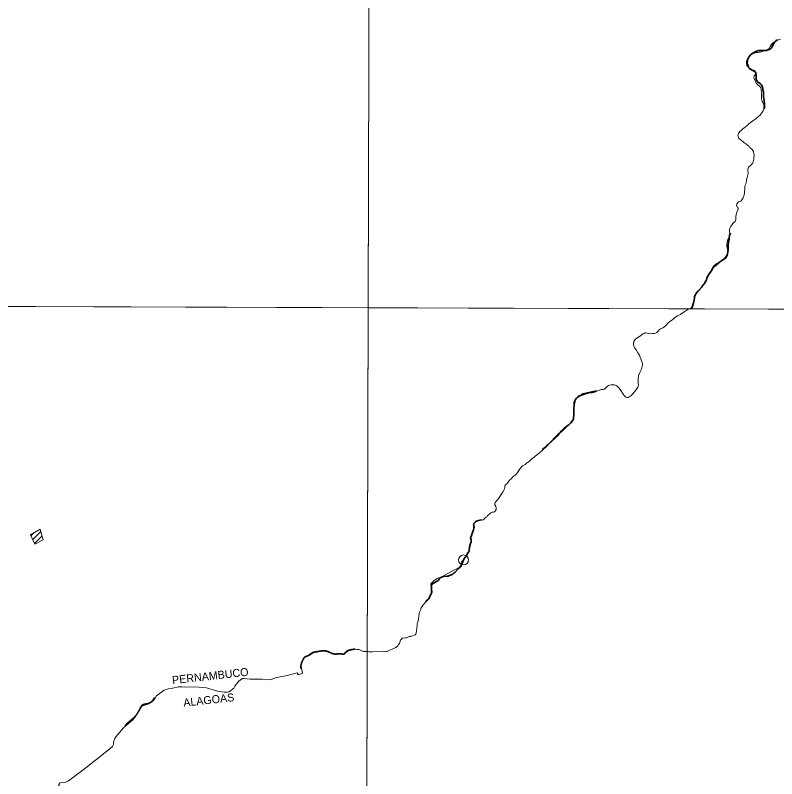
# Model space of a CAD drawing. Extents: x -1643653 to 4543381, y 1624270 to 13878484.
# Drawn here: x 582120 to 589726, y 8916321 to 8923949 of the extents above; entities that cross this region are included whole.
import ezdxf
from ezdxf.enums import TextEntityAlignment as Align

# ---------------------------------------------------------------- set-up
doc = ezdxf.new("R2010")
doc.units = 0
doc.header["$LTSCALE"] = 200
doc.header["$PDMODE"] = 32
doc.header["$PDSIZE"] = 100
doc.linetypes.add('LONG_DASH_SHORT_DASH', pattern=[9.9, 6, -1.2, 1.5, -1.2])
doc.layers.add('1', color=7, linetype='Continuous', lineweight=13)
doc.layers.add('6', color=7, linetype='Continuous', lineweight=13)

msp = doc.modelspace()

# ---------------------------------------------------------------- linework, layer by layer
at = {"layer": '1', "lineweight": 25}
msp.add_spline([(814781, 9009175.5), (814787.2, 9009173.4), (814796.9, 9009173.4), (814799.4, 9009172.4), (814805.1, 9009174.5), (814805.6, 9009176.5), (814811.7, 9009179.5), (814811.7, 9009179.5), (814801.5, 9009181), (814790.7, 9009181.5), (814784.1, 9009183.1), (814777.4, 9009185.1), (814778.4, 9009175.5)], degree=3, dxfattribs=at)
at = {"layer": '6'}
for p, q in [((582276.5, 8918748), (582308.9, 8918780.4)), ((582294.7, 8918709.6), (582376.4, 8918791.3)), ((582312.9, 8918671.2), (582388.6, 8918746.9))]:
    msp.add_line(p, q, dxfattribs=at)
at = {"layer": '6', "linetype": 'LONG_DASH_SHORT_DASH', "lineweight": 35}
msp.add_line((585799, 8917597.9), (585799.3, 8917597.8), dxfattribs=at)
at = {"layer": '6'}
for points in [[(585656.3, 8924738.8), (585614.8, 8909969.8), (585573.6, 8896026.7)], [(589516.7, 8923577.1), (589538.1, 8923578.1), (589548.8, 8923580.6), (589560.2, 8923581.6), (589569.4, 8923583.3), (589579.4, 8923585.8), (589590.3, 8923590.3), (589607, 8923592.8), (589610.7, 8923593), (589621.2, 8923596.4), (589631.2, 8923602.7), (589640.6, 8923608.9), (589649, 8923617.2), (589661.2, 8923635.9), (589671.7, 8923653.4), (589678, 8923660.6), (589684.5, 8923668.9), (589692.2, 8923676.6), (589712.7, 8923690.4), (589723, 8923695), (589763.3, 8923710.2)], [(589500.8, 8923316.4), (589497.4, 8923327.4), (589499.4, 8923339.3), (589501, 8923341.2), (589502, 8923343.6), (589509.3, 8923353.2), (589510.9, 8923357.4), (589513.7, 8923360.2), (589514.2, 8923361.5), (589515.2, 8923369.6), (589514, 8923378.3), (589507.6, 8923392.2), (589502.1, 8923396.1), (589495.2, 8923398.9), (589475, 8923406.2), (589463.6, 8923412.9), (589453.8, 8923420.2), (589443.6, 8923429), (589435.7, 8923436.2), (589428.2, 8923446.1), (589425.5, 8923454), (589424.1, 8923463.2), (589422.2, 8923489.5), (589423.2, 8923490.8), (589430, 8923506.7), (589434.9, 8923512.9), (589439.6, 8923519.5), (589449.5, 8923531.9), (589454.7, 8923539.7), (589458.4, 8923543.1), (589459.4, 8923547.2), (589461.9, 8923548.3), (589474.8, 8923558.2), (589516.7, 8923577.1)], [(589512.2, 8923285.9), (589505.5, 8923301.3), (589500.8, 8923316.4)], [(589338.9, 8922741.2), (589338.8, 8922746.3), (589340.7, 8922759.1), (589343.2, 8922767.2), (589348.9, 8922777), (589356.6, 8922785.8), (589359.8, 8922791.1), (589362.2, 8922793.4), (589369.6, 8922799), (589373.1, 8922802.4), (589379.9, 8922807.3), (589387.7, 8922815.1), (589392.1, 8922817.7), (589396.6, 8922820.9), (589400.9, 8922823.2), (589407.8, 8922827.8), (589410.8, 8922830), (589417.8, 8922837), (589427.9, 8922845.1), (589432.4, 8922849.7), (589443.9, 8922858.7), (589448.7, 8922863.3), (589478.5, 8922888.2), (589483.8, 8922891.4), (589496.7, 8922900.7), (589507.2, 8922907.3), (589516.2, 8922913.7), (589520.7, 8922917.5), (589525.2, 8922921.8), (589536.8, 8922931.1), (589539.5, 8922934.5), (589544.3, 8922939.2), (589547.5, 8922941.3), (589550.8, 8922944.3), (589556, 8922947.7), (589559.1, 8922950.1), (589567.9, 8922959.8), (589570.8, 8922963.9), (589573.4, 8922969), (589575.7, 8922972.4), (589584.2, 8922983.5), (589586.3, 8922987.3), (589589.4, 8922994.1), (589591.3, 8923001.8), (589593.9, 8923009.7), (589595.6, 8923016.5), (589598.2, 8923032.3), (589598.3, 8923038.9), (589598.8, 8923046), (589598.1, 8923052), (589594.3, 8923064.6), (589586.6, 8923077.4), (589581.5, 8923087.3), (589579.4, 8923090.2), (589576.8, 8923096.9), (589574.8, 8923115.9), (589574.7, 8923128.7), (589572.2, 8923141.7), (589572.1, 8923166.5), (589571.4, 8923174.8), (589572, 8923181.2), (589572, 8923187.4), (589570.7, 8923193.9), (589570.6, 8923200.3), (589569.4, 8923206.9), (589568.7, 8923215.2), (589566.8, 8923223.1), (589565.5, 8923223.8), (589565.2, 8923226.3), (589560, 8923234), (589552.3, 8923240.3), (589538.4, 8923254.4), (589519, 8923270.7), (589512.2, 8923285.9)], [(589460.2, 8922445.9), (589466.4, 8922450.1), (589476.2, 8922460.4), (589478.9, 8922461), (589479.3, 8922463.1), (589485.5, 8922471.9), (589489.5, 8922483.1), (589494.3, 8922502.3), (589496.3, 8922513.2), (589498.7, 8922533.1), (589498.8, 8922543.7), (589499.9, 8922553.6), (589498.6, 8922564.5), (589495.3, 8922585.8), (589493.7, 8922587.8), (589487.6, 8922597.4), (589480, 8922606.1), (589458, 8922627), (589457.7, 8922628.5), (589456.1, 8922628.9), (589455.7, 8922631.9), (589451.9, 8922634.7), (589447.8, 8922642.2), (589427.8, 8922657), (589418, 8922663.8), (589407.5, 8922670.3), (589398, 8922677.1), (589389.1, 8922685.1), (589376.8, 8922695.6), (589372.3, 8922698.8), (589371.6, 8922700.5), (589347.3, 8922716.4), (589346.4, 8922718.1), (589338.9, 8922741.2)], [(589006.9, 8921286.1), (589017.7, 8921298.2), (589025.9, 8921311.4), (589032.3, 8921323.1), (589038.7, 8921335.9), (589044.8, 8921346.8), (589061.1, 8921374.5), (589062.1, 8921375.7), (589065.5, 8921376.8), (589066.3, 8921377.4), (589067.9, 8921382.3), (589080.2, 8921406.4), (589088.1, 8921416.9), (589095.6, 8921428.2), (589103, 8921436.9), (589114.8, 8921446.2), (589127.9, 8921454.3), (589138.6, 8921462.4), (589156.6, 8921481.7), (589166.2, 8921490.8), (589178.1, 8921500.6), (589191.4, 8921510), (589200.1, 8921518.9), (589210.1, 8921529.4), (589229.5, 8921558.3), (589234.5, 8921575.8), (589235.7, 8921589), (589233, 8921614.5), (589230.5, 8921626.8), (589227.1, 8921641), (589225.9, 8921651.4), (589226.5, 8921662.7), (589229.7, 8921674.9), (589234.2, 8921697.9), (589238.6, 8921709.2), (589245.8, 8921721.4), (589253.2, 8921743.4), (589255.8, 8921757.4), (589255.8, 8921769.2), (589254.4, 8921783), (589254.5, 8921808.2), (589258.8, 8921821.3), (589264.6, 8921833.6), (589274, 8921849.4), (589285.7, 8921867.3), (589287, 8921868.7), (589298.2, 8921877), (589311.8, 8921888.1), (589315.3, 8921895.6), (589317.8, 8921908.2), (589317.8, 8921921), (589318.4, 8921933.5), (589321, 8921959.8), (589324.1, 8921972.4), (589328.4, 8921984.8), (589339.9, 8922008.6), (589340.7, 8922010.8), (589340.6, 8922020.6), (589340.4, 8922021.9), (589337.5, 8922025.1), (589335.1, 8922031.9), (589330.5, 8922037.5), (589325.3, 8922042.9), (589326.5, 8922064), (589345, 8922085.2), (589367.2, 8922093.1), (589369, 8922094.1), (589390.3, 8922123.7), (589395, 8922136.7), (589398.9, 8922149.8), (589403.8, 8922174.9), (589403.9, 8922188.4), (589406.4, 8922213.6), (589406.4, 8922226.6), (589408.3, 8922239.4), (589411.4, 8922251.8), (589416.5, 8922265), (589419.7, 8922277.8), (589423.4, 8922290.4), (589424.8, 8922303.8), (589429.7, 8922328.4), (589434.3, 8922342), (589437.6, 8922355.6), (589439.4, 8922368.3), (589439.3, 8922380.6), (589438, 8922393.7), (589438.1, 8922406.5), (589445.3, 8922432.1), (589460.2, 8922445.9)], [(588894.1, 8921078.3), (588899.6, 8921098.8), (588904.2, 8921126.1), (588914.3, 8921152.8), (588920.1, 8921165.7), (588925.5, 8921176.6), (588933.3, 8921185.3), (588950, 8921200.7), (588958.1, 8921209.6), (588965.2, 8921218.7), (588971.4, 8921228.1), (588977.2, 8921237.7), (588983.2, 8921246), (588992.1, 8921255.2), (589001.3, 8921265.6), (589006.1, 8921273.9), (589006.9, 8921286.1)], [(574684.9, 8921064.7), (596639.8, 8920989.8), (607636.3, 8920937.2), (626625.7, 8920820.5)], [(588866, 8921014.8), (588889.6, 8921061.5), (588894.1, 8921078.3)], [(588655.6, 8920885.9), (588677.4, 8920901.9), (588686.9, 8920909.9), (588701.1, 8920923.5), (588708.3, 8920929.1), (588735.8, 8920945.1), (588763.3, 8920958.1), (588772.3, 8920964.5), (588787.3, 8920977.1), (588811.4, 8920991.1), (588822.9, 8921000.3), (588834.6, 8921008.1), (588849.2, 8921013.6), (588866, 8921014.8)], [(588133.1, 8920242.8), (588149.7, 8920226.2), (588162.1, 8920210.6), (588192.2, 8920163.2), (588200.8, 8920151.2), (588210.3, 8920141), (588218.2, 8920134.2), (588229.5, 8920131.2), (588239.4, 8920130.6), (588242.6, 8920131.2), (588252.2, 8920136.2), (588263.6, 8920144.6), (588274.1, 8920153.8), (588286.8, 8920167.4), (588317.7, 8920204.6), (588338.9, 8920234.8), (588341.5, 8920240.4), (588344.1, 8920258), (588343.1, 8920273.4), (588340.8, 8920288.6), (588341.3, 8920325.6), (588343.4, 8920340), (588346, 8920349.4), (588356.8, 8920379.2), (588371.2, 8920405), (588375.2, 8920414.2), (588383.2, 8920440), (588384.8, 8920451.4), (588384.9, 8920464.6), (588382.6, 8920479), (588371.7, 8920504.6), (588359.6, 8920544.4), (588355, 8920553.2), (588348.1, 8920563.6), (588339.4, 8920574.6), (588322.3, 8920605), (588308.9, 8920623.2), (588298.6, 8920647.4), (588295.4, 8920660.6), (588295.9, 8920674.4), (588299.2, 8920688.8), (588303.9, 8920701), (588310.3, 8920711), (588316.9, 8920717), (588354.3, 8920738), (588383.7, 8920762), (588395.1, 8920768.6), (588407.3, 8920773.8), (588413, 8920775.2), (588418.4, 8920774.8), (588460.6, 8920766.8), (588487.3, 8920768.8), (588503.7, 8920768.2), (588522.2, 8920775.8), (588526.8, 8920778.8), (588537.4, 8920788.2), (588548.5, 8920803.2), (588555.8, 8920810.9), (588564.9, 8920816.8), (588587.7, 8920826.9), (588603.8, 8920836.1), (588610.7, 8920843.9), (588624, 8920855.9), (588641.9, 8920874.5), (588655.5, 8920886.1)], [(587691.5, 8919899.2), (587695.6, 8919912), (587699.2, 8919964.2), (587697.5, 8919992.4), (587697.6, 8920004.6), (587700.8, 8920020), (587703.5, 8920044.2), (587710.4, 8920069), (587712.5, 8920094.4), (587714.5, 8920104.2), (587717.9, 8920111), (587723, 8920118), (587730.8, 8920125.6), (587748.4, 8920136.4), (587759.7, 8920142.4), (587778.2, 8920150.6), (587804, 8920160), (587849.8, 8920172.2), (587870.3, 8920176.6), (587885.6, 8920178.2), (587910.3, 8920183.8), (587917, 8920186.6), (587930.3, 8920193.8), (587965.5, 8920207.4), (587974.1, 8920208.8), (587989.3, 8920209.2), (587999.8, 8920211.8), (588005.2, 8920214.8), (588016.8, 8920224), (588035.3, 8920241.8), (588046.8, 8920250.6), (588055.4, 8920254.4), (588071.6, 8920256.6), (588094, 8920257.2), (588104.9, 8920255.8), (588121.9, 8920249.6), (588133.1, 8920242.8)], [(586916.9, 8918999.4), (586921.8, 8919011.7), (586923.2, 8919017.8), (586923.8, 8919027.8), (586919.9, 8919040.7), (586909.9, 8919057.1), (586909, 8919064.2), (586909.4, 8919069.7), (586914.4, 8919080.4), (586932.4, 8919104.2), (586949.8, 8919125.1), (586961.5, 8919140.2), (586992.8, 8919190.2), (587002.7, 8919209.4), (587006.2, 8919218.4), (587008.9, 8919230.4), (587010.4, 8919247.4), (587012.9, 8919254.6), (587016, 8919258.6), (587035, 8919274.8), (587055.6, 8919302.4), (587072, 8919316.4), (587094, 8919340.4), (587112.3, 8919355.2), (587126.1, 8919368.8), (587137.1, 8919382), (587155.1, 8919411), (587172.6, 8919433.8), (587187.4, 8919446.2), (587211.4, 8919462), (587226.2, 8919474.8), (587234.8, 8919481.4), (587256, 8919495), (587279.1, 8919516.8), (587302.2, 8919534.6), (587313.3, 8919545), (587338.1, 8919562.4), (587360.9, 8919581.2), (587383.5, 8919602), (587399.3, 8919618), (587418.7, 8919633.8), (587431.5, 8919646.8), (587438.1, 8919658.2), (587442.8, 8919664), (587447.3, 8919667.4), (587454, 8919670.8), (587465.3, 8919679.2), (587481.8, 8919698.6), (587488.5, 8919705), (587509.1, 8919720), (587523.9, 8919732.2), (587542.4, 8919750.6), (587556.5, 8919769.4), (587562.2, 8919775.8), (587583.5, 8919793.8), (587602, 8919814.2), (587611.3, 8919821.8), (587622.8, 8919832.8), (587643.4, 8919849.8), (587655.9, 8919864), (587663.9, 8919871.6), (587678.6, 8919882), (587683.7, 8919887), (587691.5, 8919899.2), (587691.5, 8919899.2)], [(586679.6, 8918760.5), (586680.3, 8918772.5), (586692.5, 8918786.5), (586696.8, 8918798.9), (586696.9, 8918809.3), (586697.7, 8918812.7), (586699.3, 8918815.3), (586704.2, 8918820.1), (586707.7, 8918826.9), (586707.4, 8918834.5), (586702.6, 8918847.7), (586701.8, 8918857.5), (586703.1, 8918864.1), (586709.7, 8918881.3), (586721, 8918893.5), (586725.9, 8918895.7), (586766.1, 8918904.9), (586782.2, 8918905.1), (586794.3, 8918909.1), (586801.8, 8918914.7), (586808.8, 8918923.3), (586813, 8918927.3), (586824.3, 8918933.9), (586830.1, 8918938.5), (586834.8, 8918944.1), (586841.9, 8918955.9), (586845.8, 8918960.3), (586848.8, 8918962.4), (586859.7, 8918966.8), (586863.7, 8918970.4), (586869.3, 8918977.4), (586877.2, 8918981.7), (586883.6, 8918984.1), (586895.7, 8918985.2), (586905.7, 8918987.4), (586911.9, 8918992.7), (586916.9, 8918999.4)], [(586136.8, 8917879.9), (586143.9, 8917898.3), (586146.5, 8917907.1), (586150.7, 8917947.5), (586156.3, 8917986.5), (586166.2, 8918006.3), (586175.4, 8918028.7), (586186.6, 8918050.1), (586197.8, 8918063.5), (586206.1, 8918071.9), (586225, 8918098.7), (586234.8, 8918109.9), (586249.5, 8918120.5), (586256.8, 8918127.7), (586261.3, 8918135.7), (586262.8, 8918149.5), (586276.3, 8918165.5), (586281.8, 8918176.7), (586282.8, 8918182.3), (586282.8, 8918191.1), (586279.2, 8918209.5), (586279.1, 8918219.3), (586275.1, 8918241.3), (586270.8, 8918255.1), (586270.6, 8918261.3), (586271.5, 8918267.7), (586278.2, 8918274.1), (586295.8, 8918294.9), (586307.4, 8918303.7), (586335.1, 8918320.1), (586377.8, 8918336.7), (586395.1, 8918344.9), (586480.1, 8918393.5), (586505.7, 8918406.7), (586524.1, 8918414.9), (586554, 8918433.1), (586568.4, 8918447.3), (586570.6, 8918451.1), (586575.7, 8918463.9), (586578.3, 8918475.3), (586579.7, 8918491.9), (586595.5, 8918507.3), (586602.8, 8918522.3), (586607.5, 8918529.5), (586619.7, 8918540.1), (586627.3, 8918548.9), (586630.1, 8918555.5), (586632.3, 8918569.5), (586634.1, 8918575.1), (586636.7, 8918579.5), (586645.9, 8918589.1), (586648.8, 8918594.9), (586650.6, 8918604.3), (586653.5, 8918631.7), (586658.1, 8918644.7), (586665.3, 8918659.3), (586672.6, 8918692.7), (586672.6, 8918710.3), (586671.1, 8918715.7), (586665.9, 8918726.3), (586666, 8918731.5), (586668, 8918736.7), (586678.5, 8918755.1), (586678.5, 8918755.1), (586679.6, 8918760.5)], [(585824.4, 8917592.5), (585835.6, 8917593.5), (585848.5, 8917598.3), (585866.6, 8917609.5), (585883, 8917614.7), (585896.8, 8917622.9), (585921, 8917633.3), (585928.7, 8917638.5), (585940.3, 8917649.7), (585947.5, 8917662.7), (585957.1, 8917673.5), (585961.2, 8917682.5), (585965.9, 8917699.7), (585968.9, 8917706.9), (585976, 8917717.1), (585984.1, 8917723.9), (585988.6, 8917725.7), (585994.5, 8917727.1), (586017.6, 8917728.5), (586028.1, 8917729.9), (586035.3, 8917731.9), (586054, 8917741.3), (586060.6, 8917742.5), (586070, 8917742.7), (586088.9, 8917750.3), (586104.1, 8917754.3), (586112.5, 8917757.7), (586118, 8917762.1), (586120.7, 8917766.5), (586122.9, 8917773.1), (586126.9, 8917800.7), (586130.7, 8917821.1), (586131.4, 8917832.3), (586133.7, 8917846.3), (586134.3, 8917870.5), (586136.8, 8917879.9)], [(584946, 8917362.1), (584956.7, 8917362.1), (584984.5, 8917371.3), (584987.1, 8917382.3), (584980.7, 8917404.5), (584974.8, 8917448.6), (584983.7, 8917481.7), (584998.1, 8917514.8), (585010.1, 8917531), (585049.8, 8917550.4), (585085.7, 8917573.9), (585106.9, 8917582), (585162.1, 8917591.8), (585206.3, 8917594.7), (585224.1, 8917592.2)], [(585406.5, 8917564.6), (585417.5, 8917578), (585441.3, 8917595.2), (585463.8, 8917604.5), (585514.8, 8917615.6), (585533.1, 8917613.4)], [(585533.1, 8917613.4), (585551.5, 8917611.2), (585597.6, 8917591.8)], [(585224.1, 8917592.2), (585233.4, 8917590.9), (585273.5, 8917573.1), (585302.3, 8917565), (585331.2, 8917562.9), (585406.5, 8917564.6)], [(585597.6, 8917591.8), (585645.8, 8917591.3), (585655.1, 8917588.7), (585668.4, 8917587.5), (585687.5, 8917587.3), (585824.4, 8917592.5)], [(584562.5, 8917316.2), (584584.8, 8917316), (584661, 8917309.7), (584679.6, 8917312.2), (584715.2, 8917328.8), (584836.7, 8917352.1), (584920.8, 8917375.9), (584935.7, 8917377.6), (584946, 8917362.1)], [(584289.7, 8917215.3), (584302.2, 8917227.5), (584311.2, 8917245.5), (584349.8, 8917291.8), (584386.3, 8917322.1), (584405.1, 8917324.1), (584466.3, 8917316.9), (584511.8, 8917316.6), (584562.5, 8917316.2)], [(583605.6, 8917205.9), (583606.2, 8917206.4), (583647.1, 8917217.9), (583691.7, 8917225.1), (583694.7, 8917225.9)], [(583694.7, 8917225.9), (583751.3, 8917239.9), (583784.8, 8917238.2)], [(583784.8, 8917238.2), (583823, 8917236.2), (583913.9, 8917240), (584030.3, 8917229.4), (584139.1, 8917197.5), (584207.1, 8917184.8), (584241.1, 8917186), (584254.7, 8917190.7), (584281.9, 8917207.8), (584289.7, 8917215.3)], [(583497.2, 8917101.5), (583513.7, 8917119.7), (583530.7, 8917150.3), (583605.6, 8917205.9)], [(583374.4, 8917029.3), (583384.1, 8917046.7), (583454.1, 8917069.1), (583484.8, 8917087.9), (583497.2, 8917101.5)], [(583110.2, 8916714.5), (583112.9, 8916723.3), (583122.7, 8916738.7), (583200.6, 8916830.8), (583293.7, 8916911.2), (583311.9, 8916931.1), (583355.3, 8916994.9), (583374.4, 8917029.3)], [(583090.8, 8916642.8), (583100.4, 8916661.6), (583101.2, 8916686.4), (583110.2, 8916714.5)], [(582550.9, 8916251), (582561.6, 8916267.1), (582557.7, 8916274.2), (582569.7, 8916279), (582618.1, 8916284.9), (582650.7, 8916300), (582838.2, 8916439.2), (582906.1, 8916497.3), (582963.8, 8916539.2), (583090.8, 8916642.8)]]:
    msp.add_lwpolyline(points, dxfattribs=at)
for points in [[(585656.3, 8924738.8), (596655.5, 8924715.8), (596639.8, 8920989.8), (585645.8, 8921027.3)], [(585645.8, 8921027.3), (574684.9, 8921064.7), (574653.9, 8910009.3), (585614.8, 8909969.8)], [(582271.3, 8918759), (582316.7, 8918663.1), (582399.6, 8918706.8), (582369.9, 8918815)]]:
    msp.add_lwpolyline(points, close=True, dxfattribs=at)
at = {"layer": '6', "linetype": 'LONG_DASH_SHORT_DASH', "lineweight": 35}
for points in [[(589732.9, 8923704.4), (589720.4, 8923696.8), (589711.9, 8923686.3), (589703.9, 8923675.2), (589686.9, 8923648.5), (589679.9, 8923633.9), (589669.4, 8923618.8), (589654.3, 8923608.2), (589639.8, 8923602.6), (589624.2, 8923598), (589606.1, 8923597.4), (589577.5, 8923597.3), (589547.8, 8923595.2), (589516.7, 8923586.5), (589487.6, 8923569.3), (589474.1, 8923560.2), (589463, 8923552.1), (589450, 8923535.5), (589443, 8923523.4), (589434.5, 8923504.3), (589433.6, 8923489.7), (589432.1, 8923474.7), (589432.2, 8923458.6), (589438.8, 8923442), (589443.9, 8923427), (589454, 8923417.5), (589481.2, 8923399), (589495.2, 8923394.6), (589508.3, 8923387.6), (589517.5, 8923372.6), (589521, 8923358.5), (589521.1, 8923325.4), (589521.7, 8923309.8), (589526.8, 8923294.8), (589535.4, 8923281.8), (589550, 8923273.8)], [(589550, 8923273.8), (589562.6, 8923262.8), (589572.7, 8923252.8), (589580.3, 8923236.7), (589585.3, 8923220.2), (589588.4, 8923200.6), (589592.5, 8923183.1), (589592.6, 8923164), (589594.7, 8923132.3), (589596.3, 8923117.3), (589599.3, 8923103.2), (589600.9, 8923089.7), (589603.5, 8923071.6), (589604, 8923056.6), (589604.1, 8923041.5), (589603.6, 8923025.4), (589601.5, 8923015.4)], [(589262.4, 8921776.3), (589254.8, 8921747.1), (589251.8, 8921726), (589251.4, 8921710.4), (589247.4, 8921693.8), (589239.5, 8921655.1), (589239.6, 8921610.4), (589237.7, 8921580.3), (589235.3, 8921563.7), (589231.3, 8921549.6), (589215.3, 8921521.4), (589132.6, 8921468.3), (589120.5, 8921461.2), (589098, 8921441), (589090.5, 8921429.4), (589084, 8921417.3), (589078.5, 8921402.8), (589050.5, 8921365.4), (589040.5, 8921350.3), (589033.5, 8921337.8), (589029, 8921322.2), (589025.5, 8921307.1), (589017.5, 8921291.5), (589010.5, 8921279.4), (589002, 8921266.3), (588982.5, 8921240.6), (588974, 8921227.5), (588964.5, 8921217.4), (588950.5, 8921205.3), (588938.9, 8921193.2), (588929.9, 8921182.6), (588918.9, 8921166.4), (588912.4, 8921152.3), (588906, 8921134.7), (588905.5, 8921121.2), (588902, 8921105.6), (588899.1, 8921090), (588894.1, 8921076.4), (588881.2, 8921032.6), (588876.7, 8921019.1), (588873.6, 8921014.8)], [(587701.6, 8920064.6), (587703.2, 8920080.8), (587707.8, 8920095.9), (587711, 8920103.7), (587715.3, 8920111.1), (587726.9, 8920123.9), (587733.5, 8920129.9), (587738.1, 8920135.1), (587744.4, 8920140.8), (587750.3, 8920144.2), (587771.1, 8920154.8), (587778.3, 8920159.7), (587792.9, 8920165.5), (587808.5, 8920171.2), (587837.1, 8920177.3), (587851.6, 8920180.9), (587880.5, 8920185.8), (587895.1, 8920188.6), (587902.5, 8920190.3), (587916.5, 8920192.8), (587924.1, 8920195.4), (587926.9, 8920195.9)], [(587384.3, 8919609.4), (587392.8, 8919616.3), (587405.5, 8919627.7), (587412.1, 8919632.4), (587417.9, 8919638.4), (587424.8, 8919644.2), (587430.4, 8919650.8), (587441.5, 8919662), (587541.8, 8919762.6), (587551.1, 8919770.1), (587557.9, 8919776), (587563.2, 8919781.1), (587576.3, 8919795.3), (587583.5, 8919804.2), (587591.3, 8919812.9), (587606.1, 8919826.6), (587612.5, 8919831.4), (587618.5, 8919836.6), (587624.4, 8919840.8), (587631.5, 8919846.6), (587642.7, 8919854.2), (587649.1, 8919858.2), (587655, 8919862.8), (587659.9, 8919868.4), (587664.8, 8919874.6), (587695.6, 8919913.3), (587697.2, 8919915.7), (587699.1, 8919965.1), (587698.6, 8919973.8), (587699.4, 8919981), (587699.3, 8919988.3), (587699.9, 8919996), (587699.5, 8920003.7), (587699.7, 8920011.4), (587699.3, 8920019.1), (587700.3, 8920027), (587701.3, 8920041), (587701.6, 8920049.7), (587701.4, 8920057.6), (587701.6, 8920064.6)], [(586698.2, 8918860.5), (586699.5, 8918868.4), (586701.6, 8918872.3), (586709.1, 8918881.7), (586716.2, 8918889), (586725.8, 8918894.1), (586735.2, 8918897.5), (586743.7, 8918899.7), (586775.5, 8918907)], [(586597.6, 8918506.7), (586605.9, 8918523.4), (586611.9, 8918529.9), (586617.3, 8918534), (586622.3, 8918538.9), (586623.4, 8918540.9), (586626.4, 8918548.8), (586631.3, 8918557.1), (586634.3, 8918565.1), (586637.8, 8918573), (586643.9, 8918581.7), (586648.8, 8918589.4), (586652.3, 8918595.6), (586654.7, 8918605.5), (586654.8, 8918613.8), (586656.7, 8918622.1), (586657.8, 8918638.2), (586659.7, 8918646.3), (586661, 8918654.2), (586663.5, 8918662.4), (586666.6, 8918670.9), (586668.9, 8918678.8), (586672.1, 8918687.1), (586672.3, 8918702.8), (586672, 8918712), (586671, 8918719.4), (586667.1, 8918727.6), (586666.9, 8918728.6), (586672.8, 8918742), (586679.1, 8918756), (586680.9, 8918764.7), (586683.4, 8918772.6), (586688.5, 8918781.8), (586690.3, 8918790.4), (586695.8, 8918807.9), (586701.3, 8918821.4), (586701.6, 8918825.4), (586701.4, 8918834.4), (586699.1, 8918851.1), (586698.2, 8918860.5)], [(586513.5, 8918384.7), (586547.2, 8918421.3), (586562.5, 8918435.2), (586568.8, 8918442), (586573.9, 8918450.3), (586577.2, 8918457.8), (586580, 8918465.9), (586583.2, 8918474), (586594.1, 8918498), (586597.6, 8918506.7)], [(586222.6, 8918087.9), (586223.9, 8918090.1), (586228.4, 8918096.1), (586236.5, 8918103.6), (586243.8, 8918110.9), (586250.2, 8918118.5), (586254.6, 8918126.4), (586260.8, 8918142.7), (586268.8, 8918158.2), (586272.8, 8918166.7), (586277.2, 8918183.1), (586278.1, 8918191.2), (586277.5, 8918199.5), (586276, 8918207.8), (586276, 8918223.7), (586276.6, 8918240), (586275.8, 8918254), (586276.7, 8918256.6), (586280.2, 8918263.9), (586287.4, 8918268.9), (586293.9, 8918272.7), (586327.8, 8918291.2), (586334.7, 8918295.4), (586343.5, 8918302.7), (586357.8, 8918319.5), (586363.1, 8918326.4), (586369.2, 8918332), (586377.3, 8918336.3), (586385.6, 8918339.6), (586393.6, 8918341.5), (586401.5, 8918342.9), (586433.8, 8918344.2), (586442.3, 8918345.8), (586450.6, 8918348.2), (586466.5, 8918353.8), (586474.8, 8918357.3), (586483.3, 8918361.6), (586490.3, 8918366.2), (586504.2, 8918377.5), (586513.5, 8918384.7)]]:
    msp.add_lwpolyline(points, dxfattribs=at)
for points in [[(584975.9, 8917417.5), (584975.5, 8917419.7), (584973.4, 8917450.5), (584981.3, 8917482.8), (584997.8, 8917518.6), (585007.8, 8917534.4), (585031.4, 8917545.1), (585065.1, 8917565.2), (585093, 8917581.7), (585131, 8917589.6), (585175.4, 8917597.4), (585208.4, 8917598.2), (585232.7, 8917594.6), (585252.1, 8917588.1), (585282.1, 8917573.1), (585320.8, 8917565.9)], [(585320.8, 8917565.9), (585379.6, 8917568.1), (585403.9, 8917567.3), (585406.1, 8917568.8), (585417.5, 8917582.4), (585451.2, 8917604.6), (585489.2, 8917612.5), (585512.1, 8917617.4)], [(583212.7, 8916848.6), (583254.2, 8916889.7), (583303.2, 8916930.2), (583370.6, 8917031.5), (583385.8, 8917055.2), (583431.4, 8917068.7), (583482, 8917092.3), (583511.3, 8917134.2)]]:
    msp.add_spline(points, degree=3, dxfattribs=at)
at = {"layer": '6'}
msp.add_point((586597.6, 8918506.7), dxfattribs=at)

# ---------------------------------------------------------------- texts
for s, p in [('PERNAMBUCO', (584071.7, 8917308.3)), ('ALAGOAS', (584056.6, 8917068.5))]:
    msp.add_text(s, height=80, rotation=6.379, dxfattribs=at).set_placement(p, align=Align.CENTER)

doc.saveas('drawing.dxf')
